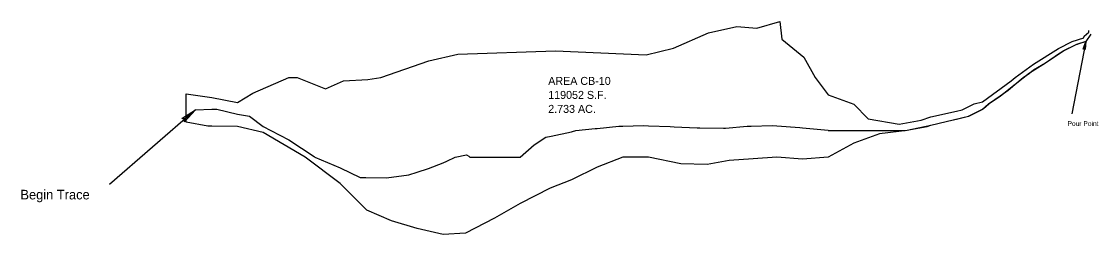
# Model space of a CAD drawing. Extents: x 2032 to 3376, y 2835 to 3102.
import ezdxf

# ---------------------------------------------------------------- set-up
doc = ezdxf.new("R2010")
doc.units = 0
for name, color, linetype in [('Default', 7, 'Continuous'), ('DESIGN - SCRATCH - User 1', 7, 'Continuous'), ('SURVEY - CENTERLINE - Preliminary', 7, 'Continuous'), ('SURVEY - CENTERLINE - Preliminary Text', 7, 'Continuous'), ('SURVEY - DRAINAGE - Area Shapes', 7, 'Continuous')]:
    doc.layers.add(name, color=color, linetype=linetype)

msp = doc.modelspace()

# ---------------------------------------------------------------- linework, layer by layer
at = {"layer": 'DESIGN - SCRATCH - User 1'}
msp.add_line((3361.7, 3076.9), (3344.1, 2986.4), dxfattribs=at)
msp.add_lwpolyline([(3361.7, 3076.9), (3361, 3066.8), (3360, 3068.3), (3358.5, 3067.2)], close=True, dxfattribs=at)
msp.add_lwpolyline([(3361.7, 3076.9), (3361, 3066.8), (3360, 3068.3), (3358.5, 3067.2), (3361.7, 3076.9)], dxfattribs=at)
at = {"layer": 'SURVEY - CENTERLINE - Preliminary'}
msp.add_lwpolyline([(2249.5, 2991.5), (2270.1, 2992.1), (2276.3, 2992.3), (2302.2, 2986.1), (2317, 2983.4), (2334.2, 2970.6), (2343.7, 2965.5), (2366.3, 2953.9), (2397.7, 2933), (2398.4, 2932.5), (2398.7, 2932.3), (2430.5, 2918.7), (2455.2, 2906.7), (2462.5, 2906.6), (2487.9, 2906.1), (2494.6, 2907.1), (2516.1, 2910.1), (2526.7, 2913.3), (2540.7, 2917.9), (2558.8, 2925.1), (2563.7, 2927.2), (2574.1, 2932.3), (2588.3, 2935), (2590.9, 2933.2), (2592.1, 2932.3), (2622.9, 2932.3), (2655, 2932.3), (2672.5, 2947.4), (2687.1, 2957.3), (2693.9, 2958.5), (2719.2, 2963.8), (2720.4, 2964.2), (2724.6, 2965.5), (2749, 2967.8), (2751.2, 2968), (2778.3, 2970.7), (2783.3, 2970.8), (2809.4, 2971.8), (2815.4, 2971.5), (2842.7, 2970.4), (2847.5, 2970.2), (2876.3, 2968.9), (2879.5, 2968.8), (2909.1, 2968.2), (2911.6, 2968.4), (2938.6, 2970.8), (2943.7, 2970.9), (2969.8, 2971.7), (2975.8, 2971.4), (3004.4, 2969.1), (3007.9, 2968.7), (3039.7, 2965.8), (3039.9, 2965.6), (3040, 2965.5), (3072, 2965.5), (3104.1, 2965.5), (3136.2, 2965.5), (3163.4, 2970.5), (3168.2, 2972.1), (3189, 2977.2), (3200.3, 2979.6), (3215, 2983.5), (3232.4, 2992.1), (3235.9, 2995.1), (3240.2, 2998.7), (3254.8, 3008.7), (3264.5, 3015.9), (3273, 3023.1), (3283.2, 3031.9), (3291.3, 3037.3), (3296.5, 3041.3), (3311.1, 3050), (3328.6, 3062), (3330.5, 3063.1), (3333.4, 3065.1), (3349.6, 3073.1), (3351.3, 3073.6), (3352.1, 3073.9), (3353.5, 3074.4), (3355.9, 3075.2), (3358.6, 3076.1), (3360.7, 3076.8), (3362, 3077.2), (3362.4, 3077.3)], dxfattribs=at)
at = {"layer": 'SURVEY - CENTERLINE - Preliminary Text'}
msp.add_line((2249.5, 2991.5), (2142.2, 2898.1), dxfattribs=at)
msp.add_lwpolyline([(2249.5, 2991.5), (2236, 2976.4), (2236.3, 2980), (2232.7, 2980.3)], close=True, dxfattribs=at)
msp.add_lwpolyline([(2249.5, 2991.5), (2236, 2976.4), (2236.3, 2980), (2232.7, 2980.3), (2249.5, 2991.5)], dxfattribs=at)
at = {"layer": 'SURVEY - DRAINAGE - Area Shapes'}
msp.add_line((2950.8, 3093.6), (2979.6, 3101.8), dxfattribs=at)
for points in [[(2541.2, 3052.5), (2577.3, 3061), (2699.3, 3065), (2812.7, 3060.1), (2846.8, 3068.3), (2890.5, 3087.8), (2925.8, 3095.4), (2950.8, 3093.6)], [(2979.6, 3101.8), (2981.9, 3079.7), (3009.6, 3057.1)], [(3009.6, 3057.1), (3023.6, 3031.9), (3039.9, 3010.2), (3072, 2998.5), (3089.9, 2980.2), (3128.4, 2973.5), (3155.9, 2978.3), (3168.2, 2982.4), (3200.3, 2989.6), (3207.3, 2991.5), (3222, 2998.7), (3232.4, 3001.4), (3268.5, 3027.7), (3273.4, 3031.9), (3296.5, 3048.3), (3327.4, 3067.9), (3344.7, 3076.6), (3359.1, 3081.4), (3359.5, 3083.4), (3365.5, 3088.4), (3365.4, 3090.4)], [(3368, 3085.9), (3361.7, 3076.9), (3349.8, 3072.9), (3334, 3065.1), (3311.4, 3049.7), (3291.5, 3037.1), (3273.2, 3022.9), (3255, 3008.5), (3240.8, 2998.7), (3236.2, 2994.8), (3232.4, 2991.6), (3215.3, 2983.2), (3168.2, 2971.7)], [(2238, 3011.2), (2270.1, 3006.6), (2302.2, 3000.4), (2321.4, 3012), (2366.3, 3031.9), (2376.5, 3031.9), (2412.1, 3017.7), (2434.5, 3027.7), (2465.1, 3029.2), (2481.1, 3031.9), (2541.2, 3052.5)], [(2450.3, 2879.2), (2430.5, 2899.1), (2386.7, 2932.3), (2334.2, 2962.9), (2302.2, 2970.5), (2270.1, 2971), (2264.9, 2970.9), (2238, 2976.1), (2238, 3011.2)], [(3168.2, 2971.7), (3138.3, 2965.5), (3104.1, 2961.4), (3072, 2949.6), (3039.7, 2932.3), (3007.9, 2929.5), (2975.8, 2932.3), (2946, 2929.9), (2916, 2927.8), (2888.8, 2922.8), (2855.8, 2923.7), (2815.4, 2932.3), (2783.3, 2932.3), (2751.2, 2919.5), (2719.2, 2903.6), (2692.8, 2893.2), (2655, 2874.2), (2622.9, 2856), (2586.7, 2837), (2558.8, 2835.4), (2526.7, 2843), (2494.6, 2852.6), (2463.5, 2865.9), (2450.3, 2879.2)]]:
    msp.add_lwpolyline(points, dxfattribs=at)

# ---------------------------------------------------------------- texts
at = {"layer": 'Default'}
for s, p in [('AREA CB-10', (2690.2, 3022.5)), ('119052 S.F.', (2690.2, 3005)), ('2.733 AC.', (2690.2, 2987.5))]:
    msp.add_text(s, height=10, dxfattribs=at).set_placement(p)
at = {"layer": 'DESIGN - SCRATCH - User 1'}
msp.add_text('Pour Point', height=6, dxfattribs=at).set_placement((3338.8, 2971.2))
at = {"layer": 'SURVEY - CENTERLINE - Preliminary Text'}
msp.add_text('Begin Trace', height=12, dxfattribs=at).set_placement((2031, 2879.3))

doc.saveas('drawing.dxf')
